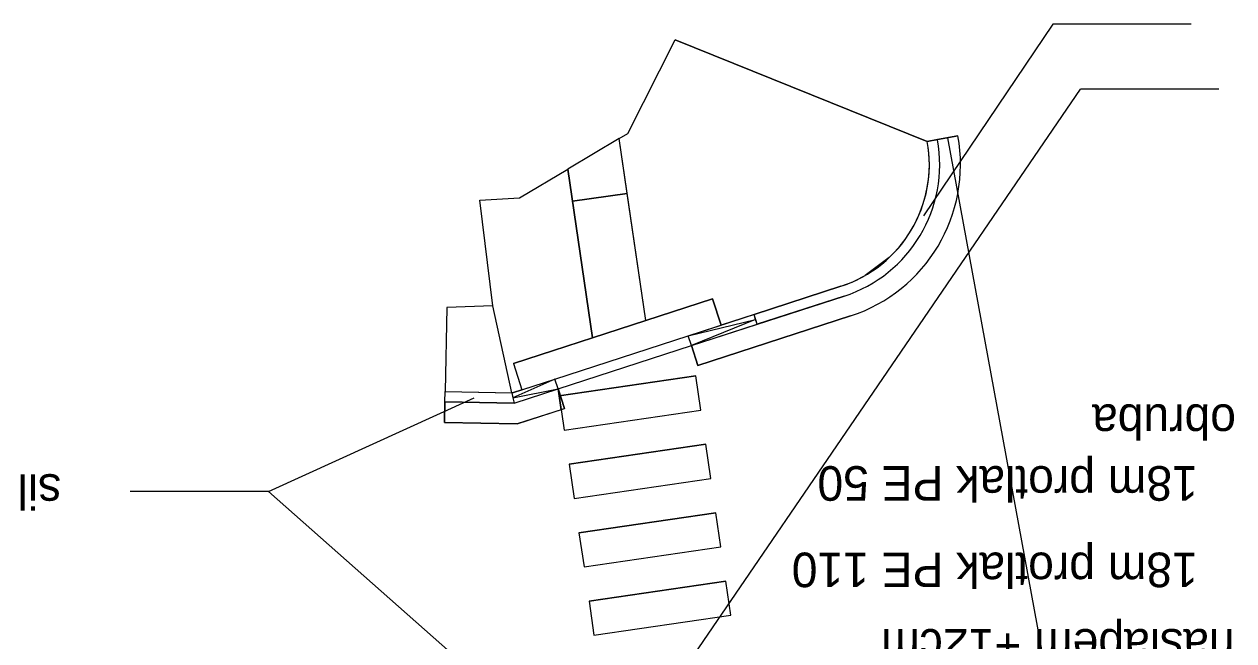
# Model space of a CAD drawing. Extents: x -728547 to -728179, y -1073068 to -1072839.
# Drawn here: x -728526.3 to -728508.81, y -1073028.16 to -1073019.25 of the extents above; entities that cross this region are included whole.
import ezdxf

# ---------------------------------------------------------------- set-up
doc = ezdxf.new("R2010")
doc.units = 0
for name, color, linetype in [('_NOR-návrh tenká', 7, 'Continuous'), ('_NOR-popis', 7, 'Continuous'), ('_NOR-VDZ', 7, 'Continuous'), ('_NOR-šraf_+12', 7, 'Continuous'), ('_NOR-šraf_chodník', 7, 'Continuous'), ('_NOR-šraf_signální pás', 7, 'Continuous'), ('_NOR-šraf_varovný pás', 7, 'Continuous'), ('_NOR-šraf_vozovka', 7, 'Continuous'), ('_NOR-šraf_zeleň', 7, 'Continuous'), ('KOS_kabelová trasa popis', 7, 'Continuous')]:
    doc.layers.add(name, color=color, linetype=linetype)

msp = doc.modelspace()

# ---------------------------------------------------------------- linework, layer by layer
at = {"layer": '_NOR-návrh tenká'}
for p, q in [((-728513.244, -1073020.944), (-728516.889, -1073019.476)), ((-728517.313, -1073023.532), (-728517.697, -1073020.9)), ((-728513.096, -1073020.917), (-728513.244, -1073020.944)), ((-728518.085, -1073023.782), (-728518.441, -1073021.342)), ((-728516.347, -1073023.219), (-728516.224, -1073023.599)), ((-728515.702, -1073023.588), (-728515.748, -1073023.445)), ((-728516.7, -1073023.753), (-728515.725, -1073023.516)), ((-728515.725, -1073023.516), (-728516.653, -1073023.896)), ((-728516.653, -1073023.896), (-728516.7, -1073023.753)), ((-728519.228, -1073024.153), (-728519.105, -1073024.534)), ((-728518.629, -1073024.379), (-728519.235, -1073024.653)), ((-728519.235, -1073024.653), (-728518.583, -1073024.522)), ((-728518.583, -1073024.522), (-728518.629, -1073024.379)), ((-728520.218, -1073024.707), (-728520.215, -1073024.557))]:
    msp.add_line(p, q, dxfattribs=at)
for points in [[(-728512.801, -1073020.863), (-728513.096, -1073020.917)], [(-728516.7, -1073023.753), (-728514.493, -1073023.037)], [(-728519.228, -1073024.153), (-728516.347, -1073023.219)], [(-728516.653, -1073023.896), (-728514.446, -1073023.18)], [(-728516.653, -1073023.896), (-728516.561, -1073024.181), (-728514.354, -1073023.465)], [(-728518.629, -1073024.379), (-728516.7, -1073023.753)], [(-728518.583, -1073024.522), (-728516.653, -1073023.896)], [(-728520.218, -1073024.707), (-728520.224, -1073025.007), (-728519.174, -1073025.029), (-728518.491, -1073024.807), (-728518.491, -1073024.807), (-728518.583, -1073024.522)], [(-728520.218, -1073024.707), (-728519.218, -1073024.728), (-728518.583, -1073024.522)], [(-728520.215, -1073024.557), (-728519.24, -1073024.577), (-728518.629, -1073024.379)]]:
    msp.add_lwpolyline(points, dxfattribs=at)
for radius in [2.3, 1.85, 2]:
    msp.add_arc((-728515.063, -1073021.278), radius, 287.972, 10.3872, dxfattribs=at)
at = {"layer": '_NOR-popis'}
for p, q in [((-728511.426, -1073019.247), (-728513.3, -1073022.018)), ((-728509.426, -1073019.247), (-728511.426, -1073019.247)), ((-728517.231, -1073029.269), (-728511.028, -1073020.188)), ((-728509.028, -1073020.188), (-728511.028, -1073020.188)), ((-728522.769, -1073026.006), (-728519.796, -1073024.65)), ((-728522.769, -1073026.006), (-728524.769, -1073026.006)), ((-728522.769, -1073026.006), (-728519.122, -1073029.229))]:
    msp.add_line(p, q, dxfattribs=at)
at = {"layer": '_NOR-VDZ'}
for p, q in [((-728518.569, -1073024.622), (-728516.59, -1073024.333)), ((-728518.496, -1073025.117), (-728516.517, -1073024.828)), ((-728518.424, -1073025.611), (-728516.445, -1073025.322)), ((-728518.352, -1073026.106), (-728516.373, -1073025.817)), ((-728518.28, -1073026.601), (-728516.301, -1073026.312)), ((-728518.207, -1073027.096), (-728516.228, -1073026.807)), ((-728518.135, -1073027.59), (-728516.156, -1073027.301)), ((-728518.063, -1073028.085), (-728516.084, -1073027.796))]:
    msp.add_line(p, q, dxfattribs=at)
for points in [[(-728512.949, -1073020.89), (-728510.942, -1073031.839)], [(-728518.496, -1073025.117), (-728516.517, -1073024.828), (-728516.59, -1073024.333), (-728518.569, -1073024.622), (-728518.496, -1073025.117), (-728518.496, -1073025.117)], [(-728518.352, -1073026.106), (-728516.373, -1073025.817), (-728516.445, -1073025.322), (-728518.424, -1073025.611), (-728518.352, -1073026.106), (-728518.352, -1073026.106)], [(-728518.207, -1073027.096), (-728516.228, -1073026.807), (-728516.301, -1073026.312), (-728518.28, -1073026.601), (-728518.207, -1073027.096), (-728518.207, -1073027.096)], [(-728518.063, -1073028.085), (-728516.084, -1073027.796), (-728516.156, -1073027.301), (-728518.135, -1073027.59), (-728518.063, -1073028.085), (-728518.063, -1073028.085)]]:
    msp.add_lwpolyline(points, dxfattribs=at)
at = {"layer": '_NOR-šraf_+12'}
for points in [[(-728513.244, -1073020.944), (-728513.096, -1073020.917)], [(-728515.748, -1073023.445), (-728514.493, -1073023.037)], [(-728514.446, -1073023.18), (-728515.702, -1073023.588), (-728515.725, -1073023.516), (-728515.748, -1073023.445), (-728515.748, -1073023.445)], [(-728520.218, -1073024.707), (-728520.215, -1073024.557), (-728519.251, -1073024.577), (-728519.235, -1073024.653), (-728519.218, -1073024.728), (-728520.218, -1073024.707)]]:
    msp.add_lwpolyline(points, dxfattribs=at)
for radius in [1.85, 2]:
    msp.add_arc((-728515.063, -1073021.278), radius, 287.972, 10.3872, dxfattribs=at)
at = {"layer": '_NOR-šraf_chodník'}
msp.add_line((-728513.793, -1073022.623), (-728514.141, -1073022.881), dxfattribs=at)
for points in [[(-728517.313, -1073023.532), (-728517.697, -1073020.9), (-728517.575, -1073020.827), (-728516.889, -1073019.476), (-728513.244, -1073020.944)], [(-728519.526, -1073023.322), (-728519.714, -1073021.793), (-728519.139, -1073021.757), (-728518.441, -1073021.342), (-728518.085, -1073023.782), (-728519.228, -1073024.153), (-728519.105, -1073024.534), (-728519.24, -1073024.577), (-728519.251, -1073024.577), (-728519.526, -1073023.322)], [(-728514.493, -1073023.037), (-728515.748, -1073023.445), (-728516.224, -1073023.599), (-728516.347, -1073023.219), (-728517.313, -1073023.532)]]:
    msp.add_lwpolyline(points, dxfattribs=at)
for start, end in [(313.3529, 10.3872), (287.972, 299.9219)]:
    msp.add_arc((-728515.063, -1073021.278), 1.85, start, end, dxfattribs=at)
at = {"layer": '_NOR-šraf_signální pás'}
for points in [[(-728518.373, -1073021.807), (-728517.581, -1073021.696), (-728517.697, -1073020.9), (-728518.441, -1073021.342), (-728518.373, -1073021.807)], [(-728517.581, -1073021.696), (-728518.373, -1073021.807), (-728518.085, -1073023.782), (-728517.313, -1073023.532), (-728517.581, -1073021.696)]]:
    msp.add_lwpolyline(points, dxfattribs=at)
at = {"layer": '_NOR-šraf_varovný pás'}
msp.add_lwpolyline([(-728518.629, -1073024.379), (-728516.7, -1073023.753), (-728516.224, -1073023.599), (-728516.347, -1073023.219), (-728517.313, -1073023.532), (-728518.085, -1073023.782), (-728519.228, -1073024.153), (-728519.105, -1073024.534), (-728518.629, -1073024.379)], dxfattribs=at)
at = {"layer": '_NOR-šraf_vozovka'}
for points in [[(-728513.096, -1073020.917), (-728512.801, -1073020.863)], [(-728516.653, -1073023.896), (-728515.702, -1073023.588), (-728514.446, -1073023.18)], [(-728514.354, -1073023.465), (-728516.561, -1073024.181), (-728516.653, -1073023.896)], [(-728518.583, -1073024.522), (-728518.539, -1073024.823), (-728519.174, -1073025.029), (-728520.224, -1073025.007), (-728520.218, -1073024.707), (-728519.218, -1073024.728), (-728518.583, -1073024.522)], [(-728518.539, -1073024.823), (-728518.583, -1073024.522), (-728518.491, -1073024.807), (-728518.539, -1073024.823)]]:
    msp.add_lwpolyline(points, dxfattribs=at)
for radius in [2.3, 2]:
    msp.add_arc((-728515.063, -1073021.278), radius, 287.972, 10.3872, dxfattribs=at)
at = {"layer": '_NOR-šraf_zeleň'}
msp.add_lwpolyline([(-728520.215, -1073024.557), (-728519.251, -1073024.577), (-728519.526, -1073023.322), (-728520.189, -1073023.343), (-728520.215, -1073024.557)], dxfattribs=at)

# ---------------------------------------------------------------- texts
at = {"layer": '_NOR-popis'}
for s, p in [('zapuštěná chodníková obruba', (-728501.902, -1073024.746)), ('silniční obruba s nášlapem +12cm', (-728525.769, -1073025.756)), ('silniční obruba s nášlapem +12cm', (-728503.781, -1073027.995))]:
    msp.add_text(s, height=0.5, rotation=180, dxfattribs=at).set_placement(p)
at = {"layer": 'KOS_kabelová trasa popis'}
for s, p in [('18m protlak PE 50', (-728509.331, -1073025.639)), ('18m protlak PE 110 ', (-728509.331, -1073026.889))]:
    msp.add_text(s, height=0.5, rotation=180, dxfattribs=at).set_placement(p)

doc.saveas('drawing.dxf')
